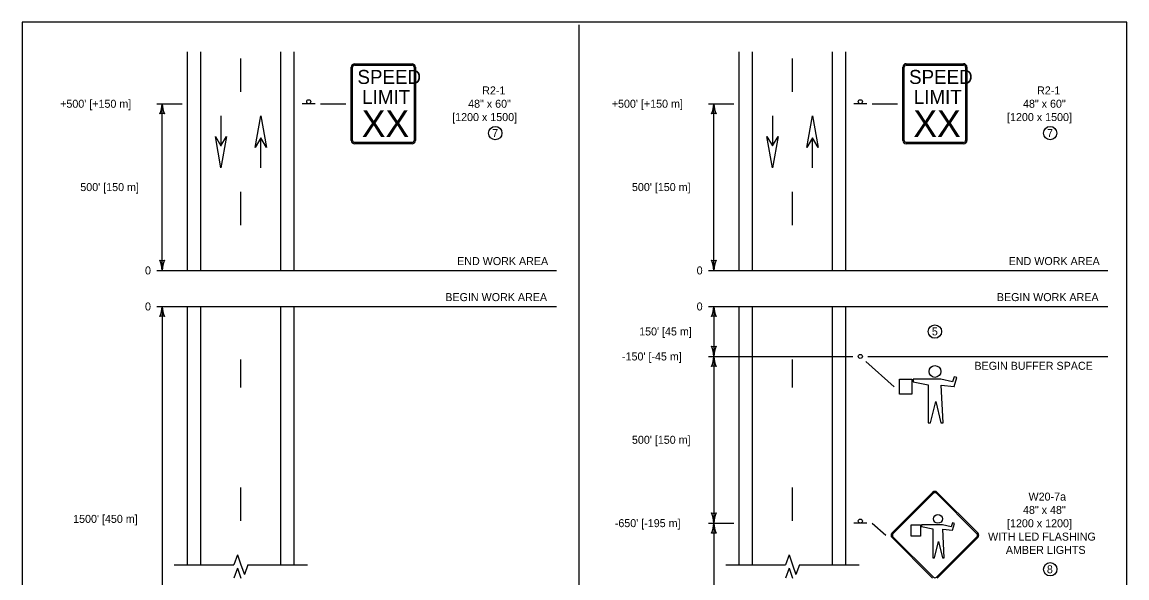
# Model space of a CAD drawing. Extents: x 49991.4 to 50021, y 49987.6 to 50011.4.
# Drawn here: x 50000.34 to 50008.61, y 50007.09 to 50011.26 of the extents above; entities that cross this region are included whole.
import ezdxf

# ---------------------------------------------------------------- set-up
doc = ezdxf.new("R2010")
doc.units = 0
for name, color, linetype in [('Level 1', 7, 'Continuous'), ('Level 2', 7, 'Continuous'), ('Level 3', 7, 'Continuous'), ('Level 6', 7, 'Continuous')]:
    doc.layers.add(name, color=color, linetype=linetype)

msp = doc.modelspace()

# ---------------------------------------------------------------- linework, layer by layer
at = {"layer": 'Level 1'}
for p, q in [((50001.5753, 50009.4004), (50001.5753, 50011.0399)), ((50001.6753, 50009.4004), (50001.6753, 50011.0399)), ((50002.2753, 50009.4004), (50002.2753, 50011.0399)), ((50002.3753, 50009.4004), (50002.3753, 50011.0399)), ((50005.7091, 50009.4004), (50005.7091, 50011.0399)), ((50005.8091, 50009.4004), (50005.8091, 50011.0399)), ((50006.4091, 50009.4004), (50006.4091, 50011.0399)), ((50006.5091, 50009.4004), (50006.5091, 50011.0399)), ((50001.9753, 50010.7408), (50001.9753, 50010.9908)), ((50006.1091, 50010.7409), (50006.1091, 50010.9909)), ((50002.8024, 50010.3753), (50002.8024, 50010.9253)), ((50002.8124, 50010.3753), (50002.8124, 50010.9253)), ((50002.8274, 50010.9503), (50003.2574, 50010.9503)), ((50002.8274, 50010.9403), (50003.2574, 50010.9403)), ((50003.2724, 50010.9253), (50003.2724, 50010.3753)), ((50003.2824, 50010.9253), (50003.2824, 50010.3753)), ((50006.9359, 50010.3754), (50006.9359, 50010.9254)), ((50006.9459, 50010.3754), (50006.9459, 50010.9254)), ((50006.9609, 50010.9504), (50007.3909, 50010.9504)), ((50006.9609, 50010.9404), (50007.3909, 50010.9404)), ((50007.4059, 50010.9254), (50007.4059, 50010.3754)), ((50007.4159, 50010.9254), (50007.4159, 50010.3754)), ((50002.5313, 50010.6503), (50002.4353, 50010.6503)), ((50006.6649, 50010.6504), (50006.5689, 50010.6504)), ((50001.8253, 50010.5593), (50001.8253, 50010.3334)), ((50001.8256, 50010.5593), (50001.8256, 50010.3334)), ((50005.9591, 50010.5594), (50005.9591, 50010.3335)), ((50005.9595, 50010.5594), (50005.9595, 50010.3335)), ((50002.125, 50010.1691), (50002.125, 50010.395)), ((50002.1253, 50010.1691), (50002.1253, 50010.395)), ((50006.2589, 50010.1692), (50006.2589, 50010.3951)), ((50006.2591, 50010.1692), (50006.2591, 50010.3951)), ((50003.2574, 50010.3603), (50002.8274, 50010.3603)), ((50003.2574, 50010.3503), (50002.8274, 50010.3503)), ((50007.3909, 50010.3604), (50006.9609, 50010.3604)), ((50007.3909, 50010.3504), (50006.9609, 50010.3504)), ((50001.9753, 50009.7408), (50001.9753, 50009.9908)), ((50006.1091, 50009.7409), (50006.1091, 50009.9909)), ((50001.5753, 50007.1935), (50001.5753, 50009.1302)), ((50001.6753, 50007.1935), (50001.6753, 50009.1302)), ((50002.2753, 50007.1935), (50002.2753, 50009.1302)), ((50002.3753, 50007.1935), (50002.3753, 50009.1302)), ((50005.7089, 50007.1935), (50005.7089, 50009.1302)), ((50005.8089, 50007.1935), (50005.8089, 50009.1302)), ((50006.4089, 50007.1935), (50006.4089, 50009.1302)), ((50006.5089, 50007.1935), (50006.5089, 50009.1302)), ((50001.9755, 50008.5231), (50001.9755, 50008.7314)), ((50006.1091, 50008.5231), (50006.1091, 50008.7314)), ((50006.9106, 50008.4721), (50006.9106, 50008.5846)), ((50006.9106, 50008.5846), (50007.0025, 50008.5846)), ((50007.0025, 50008.5846), (50007.0025, 50008.4721)), ((50007.2197, 50008.5839), (50007.0128, 50008.5839)), ((50007.0128, 50008.5839), (50007.0128, 50008.5653)), ((50007.0128, 50008.5653), (50007.1253, 50008.5431)), ((50007.3065, 50008.5639), (50007.2197, 50008.5839)), ((50007.3192, 50008.6035), (50007.3065, 50008.5639)), ((50007.3412, 50008.598), (50007.3192, 50008.6035)), ((50007.3212, 50008.5292), (50007.3412, 50008.598)), ((50007.0025, 50008.4721), (50006.9106, 50008.4721)), ((50007.1253, 50008.5431), (50007.1253, 50008.2568)), ((50007.2384, 50008.2568), (50007.2236, 50008.5402)), ((50007.2236, 50008.5402), (50007.3212, 50008.5292)), ((50007.1435, 50008.2568), (50007.1818, 50008.4181)), ((50007.1818, 50008.4181), (50007.2201, 50008.2568)), ((50007.1253, 50008.2568), (50007.1435, 50008.2568)), ((50007.2201, 50008.2568), (50007.2384, 50008.2568)), ((50001.9755, 50007.5231), (50001.9755, 50007.7731)), ((50006.1091, 50007.5231), (50006.1091, 50007.7731)), ((50007.1585, 50007.736), (50006.8544, 50007.432)), ((50007.1655, 50007.729), (50006.8615, 50007.4249)), ((50007.4908, 50007.4249), (50007.1868, 50007.729)), ((50007.4979, 50007.432), (50007.1938, 50007.736)), ((50006.6649, 50007.5052), (50006.5689, 50007.5052)), ((50006.9978, 50007.4083), (50006.9978, 50007.4933)), ((50006.9978, 50007.4933), (50007.0673, 50007.4933)), ((50007.0673, 50007.4933), (50007.0673, 50007.4083)), ((50007.2316, 50007.4929), (50007.0751, 50007.4929)), ((50007.0751, 50007.4929), (50007.0751, 50007.4788)), ((50007.0751, 50007.4788), (50007.1601, 50007.462)), ((50007.2972, 50007.4777), (50007.2316, 50007.4929)), ((50007.3068, 50007.5077), (50007.2972, 50007.4777)), ((50007.3234, 50007.5035), (50007.3068, 50007.5077)), ((50007.3083, 50007.4515), (50007.3234, 50007.5035)), ((50006.8544, 50007.3966), (50007.1585, 50007.0926)), ((50006.8615, 50007.4037), (50007.1655, 50007.0996)), ((50007.0673, 50007.4083), (50006.9978, 50007.4083)), ((50007.1601, 50007.462), (50007.1601, 50007.2455)), ((50007.1868, 50007.0996), (50007.4908, 50007.4037)), ((50007.1938, 50007.0926), (50007.4979, 50007.3966)), ((50007.2456, 50007.2455), (50007.2344, 50007.4598)), ((50007.2344, 50007.4598), (50007.3083, 50007.4515)), ((50007.1739, 50007.2455), (50007.2028, 50007.3675)), ((50007.2028, 50007.3675), (50007.2318, 50007.2455)), ((50007.1601, 50007.2455), (50007.1739, 50007.2455)), ((50007.2318, 50007.2455), (50007.2456, 50007.2455))]:
    msp.add_line(p, q, dxfattribs=at)
for points in [[(50008.6146, 50011.2628), (50000.3356, 50011.2628), (50000.3356, 50000.0624), (50008.6146, 50000.0624)], [(50002.0833, 50010.3227), (50002.125, 50010.5592), (50002.1669, 50010.3227), (50002.125, 50010.3949)], [(50006.2171, 50010.3228), (50006.2589, 50010.5593), (50006.3007, 50010.3228), (50006.2589, 50010.395)], [(50001.8673, 50010.4057), (50001.8256, 50010.1692), (50001.7837, 50010.4057), (50001.8256, 50010.3335)], [(50006.0011, 50010.4058), (50005.9595, 50010.1693), (50005.9175, 50010.4058), (50005.9595, 50010.3336)]]:
    msp.add_lwpolyline(points, close=True, dxfattribs=at)
for points in [[(50007.3191, 50008.6033), (50007.3193, 50008.6035)], [(50007.0021, 50008.4721), (50007.0025, 50008.4725)], [(50007.3206, 50008.5293), (50007.3215, 50008.5304)], [(50007.3067, 50007.5075), (50007.3068, 50007.5077)], [(50007.067, 50007.4083), (50007.0673, 50007.4086)], [(50007.3078, 50007.4516), (50007.3085, 50007.4524)]]:
    msp.add_lwpolyline(points, dxfattribs=at)
for centre, radius in [((50002.4833, 50010.6656), 0.0152), ((50006.6169, 50010.6656), 0.0152), ((50006.6169, 50008.7552), 0.0152), ((50007.176, 50008.6426), 0.0442), ((50007.1984, 50007.5373), 0.0334), ((50006.6169, 50007.5204), 0.0152)]:
    msp.add_circle(centre, radius, dxfattribs=at)
for centre, radius, start, end in [((50002.8275, 50010.9253), 0.025, 90, 180), ((50002.8275, 50010.9253), 0.015, 90, 180), ((50003.2575, 50010.9253), 0.025, 0, 90), ((50003.2575, 50010.9253), 0.015, 0, 90), ((50006.961, 50010.9254), 0.025, 90, 180), ((50006.961, 50010.9254), 0.015, 90, 180), ((50007.391, 50010.9254), 0.025, 0, 90), ((50007.391, 50010.9254), 0.015, 0, 90), ((50002.8275, 50010.3753), 0.025, 180, 270), ((50002.8275, 50010.3753), 0.015, 180, 270), ((50003.2575, 50010.3753), 0.025, 270, 0), ((50003.2575, 50010.3753), 0.015, 270, 0), ((50006.961, 50010.3754), 0.025, 180, 270), ((50006.961, 50010.3754), 0.015, 180, 270), ((50007.391, 50010.3754), 0.025, 270, 0), ((50007.391, 50010.3754), 0.015, 270, 0), ((50007.176, 50007.7184), 0.025, 45, 135), ((50007.176, 50007.7184), 0.015, 45, 135), ((50006.872, 50007.4143), 0.025, 135, 225), ((50006.872, 50007.4143), 0.015, 135, 225), ((50007.4801, 50007.4143), 0.015, 315, 45.00024), ((50007.4801, 50007.4143), 0.025, 315, 45.00024), ((50007.176, 50007.1103), 0.015, 225, 314.99957)]:
    msp.add_arc(centre, radius, start, end, dxfattribs=at)
at = {"layer": 'Level 2'}
for centre in [(50003.8817, 50010.4303), (50008.0397, 50010.4304), (50007.176, 50008.9418), (50008.0399, 50007.1591)]:
    msp.add_circle(centre, 0.05, dxfattribs=at)
at = {"layer": 'Level 3'}
for p, q in [((50004.5077, 50011.2418), (50004.5077, 50002.9277)), ((50001.3453, 50010.6503), (50001.5353, 50010.6503)), ((50001.3853, 50010.0253), (50001.3853, 50010.6503)), ((50002.5713, 50010.6503), (50002.7624, 50010.6503)), ((50005.4791, 50010.6504), (50005.6691, 50010.6504)), ((50005.5191, 50010.0254), (50005.5191, 50010.6504)), ((50006.7049, 50010.6504), (50006.8959, 50010.6504)), ((50001.3853, 50009.4004), (50001.3853, 50010.0253)), ((50005.5191, 50009.4004), (50005.5191, 50010.0254)), ((50001.3453, 50009.4004), (50002.9765, 50009.4004)), ((50002.9765, 50009.4004), (50004.3392, 50009.4004)), ((50005.4791, 50009.4004), (50007.0937, 50009.4004)), ((50007.0937, 50009.4004), (50008.4725, 50009.4004)), ((50001.3453, 50009.1302), (50002.4873, 50009.1302)), ((50001.3853, 50009.1302), (50001.3853, 50008.5052)), ((50002.4873, 50009.1302), (50004.3393, 50009.1302)), ((50005.479, 50009.1302), (50006.797, 50009.1302)), ((50005.5191, 50009.1302), (50005.5191, 50008.7552)), ((50006.797, 50009.1302), (50008.4725, 50009.1302)), ((50005.479, 50008.7552), (50006.5617, 50008.7552)), ((50005.5191, 50008.7552), (50005.5191, 50007.8802)), ((50006.6721, 50008.7552), (50008.4725, 50008.7552)), ((50006.8706, 50008.5283), (50006.6581, 50008.7184)), ((50001.3853, 50008.5052), (50001.3853, 50007.0182)), ((50005.5191, 50007.8802), (50005.5191, 50007.5052)), ((50005.479, 50007.5052), (50005.6689, 50007.5052)), ((50005.5191, 50007.5052), (50005.5191, 50007.0221)), ((50006.7049, 50007.5052), (50006.807, 50007.4143))]:
    msp.add_line(p, q, dxfattribs=at)
for centre, radius, start, end in [((50001.1632, 50010.6595), 0.2223, 337.45601, 357.63952), ((50001.618, 50010.6618), 0.233, 182.82731, 202.07716), ((50005.2969, 50010.6596), 0.2223, 337.45601, 357.63952), ((50005.7518, 50010.6619), 0.233, 182.82731, 202.07716), ((50001.3853, 50010.5221), 0.0548, 72.13882, 107.86118), ((50005.5191, 50010.5222), 0.0548, 72.13882, 107.86118), ((50001.3853, 50009.5286), 0.0548, 252.13882, 287.86118), ((50001.1526, 50009.3889), 0.233, 2.82731, 22.07716), ((50001.6075, 50009.3912), 0.2223, 157.45601, 177.63952), ((50005.5191, 50009.5286), 0.0548, 252.13882, 287.86118), ((50005.2864, 50009.3889), 0.233, 2.82731, 22.07716), ((50005.7412, 50009.3912), 0.2223, 157.45601, 177.63952), ((50001.1632, 50009.1393), 0.2223, 337.45601, 357.63952), ((50001.3853, 50009.002), 0.0548, 72.13882, 107.86118), ((50001.618, 50009.1417), 0.233, 182.82731, 202.07716), ((50005.2969, 50009.1393), 0.2223, 337.45601, 357.63952), ((50005.5191, 50009.002), 0.0548, 72.13882, 107.86118), ((50005.7518, 50009.1417), 0.233, 182.82731, 202.07716), ((50005.2969, 50008.746), 0.2223, 2.36048, 22.54399), ((50005.5191, 50008.8834), 0.0548, 252.13882, 287.86118), ((50005.7518, 50008.7437), 0.233, 157.92284, 177.17269), ((50005.2969, 50008.7643), 0.2223, 337.45601, 357.63952), ((50005.7518, 50008.7667), 0.233, 182.82731, 202.07716), ((50005.5191, 50008.627), 0.0548, 72.13882, 107.86118), ((50005.2969, 50007.496), 0.2223, 2.36048, 22.54399), ((50005.5191, 50007.6334), 0.0548, 252.13882, 287.86118), ((50005.7518, 50007.4937), 0.233, 157.92284, 177.17269), ((50005.2969, 50007.5143), 0.2223, 337.45601, 357.63952), ((50005.7518, 50007.5167), 0.233, 182.82731, 202.07716), ((50005.5191, 50007.377), 0.0548, 72.13882, 107.86118)]:
    msp.add_arc(centre, radius, start, end, dxfattribs=at)
at = {"layer": 'Level 6'}
for p, q in [((50001.9494, 50007.2666), (50001.9235, 50007.1935)), ((50001.9494, 50007.2666), (50001.9753, 50007.1935)), ((50006.083, 50007.2666), (50006.0571, 50007.1935)), ((50006.083, 50007.2666), (50006.1089, 50007.1935)), ((50001.4753, 50007.1935), (50001.9235, 50007.1935)), ((50001.9494, 50007.1666), (50001.9235, 50007.0935)), ((50001.9494, 50007.1666), (50001.9753, 50007.0935)), ((50001.9753, 50007.1935), (50002.0012, 50007.1204)), ((50002.0271, 50007.1935), (50002.0012, 50007.1204)), ((50002.0271, 50007.1935), (50002.4753, 50007.1935)), ((50005.6089, 50007.1935), (50006.0571, 50007.1935)), ((50006.083, 50007.1666), (50006.0571, 50007.0935)), ((50006.083, 50007.1666), (50006.1089, 50007.0935)), ((50006.1089, 50007.1935), (50006.1348, 50007.1204)), ((50006.1607, 50007.1935), (50006.1348, 50007.1204)), ((50006.1607, 50007.1935), (50006.6089, 50007.1935))]:
    msp.add_line(p, q, dxfattribs=at)

# ---------------------------------------------------------------- texts
at = {"layer": 'Level 1'}
for s, height, p in [('SPEED', 0.10512, (50002.8487, 50010.7988)), ('SPEED', 0.10512, (50006.9821, 50010.7989)), ('LIMIT', 0.10512, (50002.8841, 50010.6487)), ('LIMIT', 0.10512, (50007.0176, 50010.6488)), ('XX', 0.1989, (50002.8809, 50010.4014)), ('XX', 0.1989, (50007.0144, 50010.4015))]:
    msp.add_text(s, height=height, dxfattribs=at).set_placement(p)
at = {"layer": 'Level 2'}
for s, p in [('R2-1', (50003.7835, 50010.7203)), ('R2-1', (50007.9415, 50010.7204)), ("+500' [+150 m]", (50000.6207, 50010.6203)), ('48" x 60"', (50003.678, 50010.6203)), ("+500' [+150 m]", (50004.7545, 50010.6204)), ('48" x 60"', (50007.836, 50010.6204)), ('[1200 x 1500]', (50003.5585, 50010.5203)), ('[1200 x 1500]', (50007.7165, 50010.5204)), ('7', (50003.8579, 50010.4003)), ('7', (50008.0159, 50010.4004)), ("500' [150 m]", (50000.772, 50009.9953)), ("500' [150 m]", (50004.9057, 50009.9954)), ('END WORK AREA', (50003.5956, 50009.4404)), ('END WORK AREA', (50007.7288, 50009.4404)), ('0', (50001.2567, 50009.3704)), ('0', (50005.3905, 50009.3704)), ('BEGIN WORK AREA', (50003.5071, 50009.1702)), ('BEGIN WORK AREA', (50007.6402, 50009.1702)), ('0', (50001.2567, 50009.1002)), ('0', (50005.3905, 50009.1002)), ("150' [45 m]", (50004.9596, 50008.9127)), ('5', (50007.1529, 50008.9131)), ("-150' [-45 m]", (50004.831, 50008.7252)), ('BEGIN BUFFER SPACE', (50007.4719, 50008.6552)), ("500' [150 m]", (50004.9057, 50008.1002)), ('W20-7a', (50007.8774, 50007.6742)), ("1500' [450 m]", (50000.7181, 50007.5072)), ('48" x 48"', (50007.836, 50007.5742)), ("-650' [-195 m]", (50004.7771, 50007.4752)), ('[1200 x 1200]', (50007.7165, 50007.4742)), ('WITH LED FLASHING', (50007.5743, 50007.3742)), ('AMBER LIGHTS', (50007.7075, 50007.2742)), ('8', (50008.015, 50007.1292))]:
    msp.add_text(s, height=0.06, dxfattribs=at).set_placement(p)

doc.saveas('drawing.dxf')
